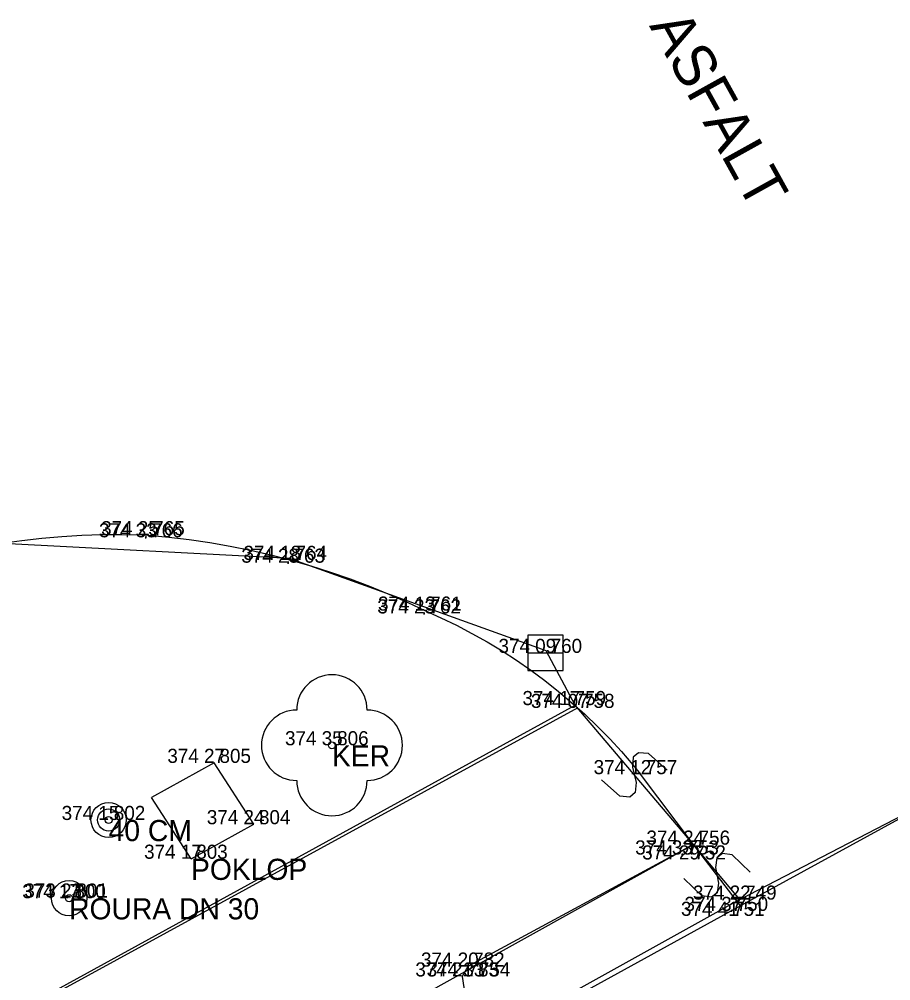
# Model space of a CAD drawing. Extents: x -601196 to -600262, y -1082523 to -1081922.
# Drawn here: x -600539.1 to -600526.73, y -1082122.59 to -1082108.95 of the extents above; entities that cross this region are included whole.
import ezdxf

# ---------------------------------------------------------------- set-up
doc = ezdxf.new("R2010")
doc.units = 0
for name, color, linetype in [('Vrstva 1', 7, 'Continuous'), ('Vrstva 10', 7, 'Continuous'), ('Vrstva 11', 7, 'Continuous'), ('Vrstva 2', 7, 'Continuous'), ('Vrstva 20', 7, 'Continuous'), ('Vrstva 22', 7, 'Continuous'), ('Vrstva 25', 7, 'Continuous'), ('Vrstva 27', 7, 'Continuous'), ('Vrstva 3', 7, 'Continuous'), ('Vrstva 40', 7, 'Continuous'), ('Vrstva 47', 7, 'Continuous'), ('Vrstva 5', 7, 'Continuous'), ('Vrstva 63', 7, 'Continuous')]:
    doc.layers.add(name, color=color, linetype=linetype)

msp = doc.modelspace()

# ---------------------------------------------------------------- linework, layer by layer
at = {"layer": 'Vrstva 1'}
for p, q in [((-600537.3, -1082116.3), (-600537.3, -1082116.3)), ((-600537.27, -1082116.27), (-600537.27, -1082116.27)), ((-600535.25, -1082116.62), (-600535.25, -1082116.62)), ((-600535.28, -1082116.66), (-600535.28, -1082116.66)), ((-600533.34, -1082117.34), (-600533.34, -1082117.34)), ((-600533.35, -1082117.38), (-600533.35, -1082117.38)), ((-600531.63, -1082117.94), (-600531.63, -1082117.94)), ((-600531.29, -1082118.68), (-600531.29, -1082118.68)), ((-600531.17, -1082118.72), (-600531.17, -1082118.72)), ((-600534.66, -1082119.25), (-600534.66, -1082119.25)), ((-600536.33, -1082119.5), (-600536.33, -1082119.5)), ((-600530.28, -1082119.66), (-600530.28, -1082119.66)), ((-600537.83, -1082120.31), (-600537.83, -1082120.31)), ((-600535.77, -1082120.37), (-600535.77, -1082120.37)), ((-600529.53, -1082120.66), (-600529.53, -1082120.66)), ((-600536.66, -1082120.86), (-600536.66, -1082120.86)), ((-600529.69, -1082120.8), (-600529.69, -1082120.8)), ((-600529.59, -1082120.87), (-600529.59, -1082120.87)), ((-600538.39, -1082121.42), (-600538.39, -1082121.42)), ((-600538.36, -1082121.41), (-600538.36, -1082121.41)), ((-600528.87, -1082121.44), (-600528.87, -1082121.44)), ((-600529.04, -1082121.67), (-600529.04, -1082121.67)), ((-600528.99, -1082121.6), (-600528.99, -1082121.6)), ((-600532.73, -1082122.39), (-600532.73, -1082122.39)), ((-600532.81, -1082122.53), (-600532.81, -1082122.53)), ((-600532.65, -1082122.53), (-600532.65, -1082122.53))]:
    msp.add_line(p, q, dxfattribs=at)
at = {"layer": 'Vrstva 10'}
for p, q in [((-600529.53, -1082120.66), (-600530.28, -1082119.66)), ((-600528.87, -1082121.44), (-600529.53, -1082120.66))]:
    msp.add_line(p, q, dxfattribs=at)
for points in [[(-600541.8, -1082117.1), (-600541.537, -1082116.99), (-600541.271, -1082116.888), (-600541.002, -1082116.793), (-600540.731, -1082116.706), (-600540.457, -1082116.626), (-600540.182, -1082116.554), (-600539.904, -1082116.49), (-600539.625, -1082116.433), (-600539.344, -1082116.385), (-600539.062, -1082116.344), (-600538.779, -1082116.311), (-600538.495, -1082116.286), (-600538.21, -1082116.269), (-600537.925, -1082116.26), (-600537.64, -1082116.259), (-600537.356, -1082116.266), (-600537.27, -1082116.27)], [(-600537.27, -1082116.27), (-600536.977, -1082116.297), (-600536.685, -1082116.331), (-600536.394, -1082116.374), (-600536.104, -1082116.424), (-600535.815, -1082116.482), (-600535.528, -1082116.548), (-600535.243, -1082116.622), (-600534.96, -1082116.703), (-600534.68, -1082116.792), (-600534.402, -1082116.889), (-600534.127, -1082116.993), (-600533.854, -1082117.105), (-600533.585, -1082117.224), (-600533.34, -1082117.34)], [(-600533.34, -1082117.34), (-600533.114, -1082117.44), (-600532.892, -1082117.547), (-600532.673, -1082117.662), (-600532.458, -1082117.783), (-600532.246, -1082117.911), (-600532.039, -1082118.045), (-600531.835, -1082118.186), (-600531.637, -1082118.333), (-600531.443, -1082118.487), (-600531.254, -1082118.646), (-600531.07, -1082118.811), (-600530.891, -1082118.982), (-600530.718, -1082119.159), (-600530.551, -1082119.34), (-600530.389, -1082119.527), (-600530.28, -1082119.66)]]:
    msp.add_lwpolyline(points, dxfattribs=at)
at = {"layer": 'Vrstva 11'}
for p, q in [((-600531.17, -1082118.72), (-600547.47, -1082127.62)), ((-600536.33, -1082119.5), (-600537.22, -1082119.99)), ((-600535.77, -1082120.37), (-600536.33, -1082119.5)), ((-600536.66, -1082120.86), (-600537.22, -1082119.99)), ((-600536.66, -1082120.86), (-600535.77, -1082120.37)), ((-600529.53, -1082120.66), (-600532.73, -1082122.39)), ((-600532.73, -1082122.39), (-600532.81, -1082122.53)), ((-600532.81, -1082122.53), (-600532.65, -1082123.58))]:
    msp.add_line(p, q, dxfattribs=at)
at = {"layer": 'Vrstva 20'}
for p, q in [((-600537.31, -1082116.3), (-600537.29, -1082116.3)), ((-600537.3, -1082116.285), (-600537.3, -1082116.3)), ((-600537.3, -1082116.315), (-600537.3, -1082116.3)), ((-600535.28, -1082116.645), (-600535.28, -1082116.66)), ((-600535.29, -1082116.66), (-600535.27, -1082116.66)), ((-600535.28, -1082116.675), (-600535.28, -1082116.66)), ((-600533.36, -1082117.38), (-600533.34, -1082117.38)), ((-600533.35, -1082117.365), (-600533.35, -1082117.38)), ((-600533.35, -1082117.395), (-600533.35, -1082117.38)), ((-600531.3, -1082118.68), (-600531.28, -1082118.68)), ((-600531.29, -1082118.665), (-600531.29, -1082118.68)), ((-600531.29, -1082118.695), (-600531.29, -1082118.68)), ((-600529.7, -1082120.8), (-600529.68, -1082120.8)), ((-600529.69, -1082120.785), (-600529.69, -1082120.8)), ((-600529.69, -1082120.815), (-600529.69, -1082120.8)), ((-600529, -1082121.6), (-600528.98, -1082121.6)), ((-600528.99, -1082121.585), (-600528.99, -1082121.6)), ((-600528.99, -1082121.615), (-600528.99, -1082121.6))]:
    msp.add_line(p, q, dxfattribs=at)
at = {"layer": 'Vrstva 22'}
msp.add_circle((-600534.66, -1082119.25), 0.05, dxfattribs=at)
for centre, start, end in [((-600534.66, -1082118.75), 0, 180), ((-600535.16, -1082119.25), 90, 270), ((-600534.16, -1082119.25), 270, 90), ((-600534.66, -1082119.75), 180, 0)]:
    msp.add_arc(centre, 0.5, start, end, dxfattribs=at)
at = {"layer": 'Vrstva 25'}
for centre, radius in [((-600537.83, -1082120.31), 0.25), ((-600537.83, -1082120.31), 0.158), ((-600537.83, -1082120.31), 0.05), ((-600538.39, -1082121.42), 0.25), ((-600538.39, -1082121.42), 0.05)]:
    msp.add_circle(centre, radius, dxfattribs=at)
at = {"layer": 'Vrstva 27'}
msp.add_line((-600531.88, -1082117.94), (-600531.38, -1082117.94), dxfattribs=at)
msp.add_lwpolyline([(-600531.88, -1082118.19), (-600531.38, -1082118.19), (-600531.38, -1082117.69), (-600531.88, -1082117.69)], close=True, dxfattribs=at)
at = {"layer": 'Vrstva 47'}
for p, q in [((-600535.26, -1082116.6), (-600539.24, -1082116.39)), ((-600531.62, -1082117.91), (-600535.26, -1082116.6)), ((-600531.21, -1082118.68), (-600531.62, -1082117.91)), ((-600547.4, -1082127.56), (-600531.21, -1082118.68)), ((-600529.53, -1082120.66), (-600531.21, -1082118.68)), ((-600530.308, -1082119.355), (-600530.385, -1082119.42)), ((-600530.167, -1082119.367), (-600530.308, -1082119.355)), ((-600529.903, -1082119.601), (-600530.167, -1082119.367)), ((-600530.385, -1082119.42), (-600530.396, -1082119.561)), ((-600530.396, -1082119.561), (-600530.343, -1082119.778)), ((-600525.4, -1082119.63), (-600528.86, -1082121.53)), ((-600530.572, -1082119.972), (-600530.836, -1082119.738)), ((-600530.343, -1082119.778), (-600530.354, -1082119.919)), ((-600530.354, -1082119.919), (-600530.431, -1082119.984)), ((-600530.431, -1082119.984), (-600530.572, -1082119.972)), ((-600546.73, -1082130.21), (-600529.53, -1082120.66)), ((-600528.86, -1082121.53), (-600529.53, -1082120.66)), ((-600529.198, -1082120.845), (-600529.216, -1082120.985)), ((-600529.118, -1082120.784), (-600529.198, -1082120.845)), ((-600528.978, -1082120.802), (-600529.118, -1082120.784)), ((-600528.725, -1082121.049), (-600528.978, -1082120.802)), ((-600529.216, -1082120.985), (-600529.173, -1082121.204)), ((-600529.411, -1082121.387), (-600529.664, -1082121.14)), ((-600529.173, -1082121.204), (-600529.191, -1082121.344)), ((-600529.271, -1082121.406), (-600529.411, -1082121.387)), ((-600529.191, -1082121.344), (-600529.271, -1082121.406)), ((-600528.86, -1082121.53), (-600545.34, -1082130.56))]:
    msp.add_line(p, q, dxfattribs=at)
at = {"layer": 'Vrstva 5'}
for q in [(-600525.37, -1082119.62), (-600545.37, -1082130.57)]:
    msp.add_line((-600528.87, -1082121.44), q, dxfattribs=at)

# ---------------------------------------------------------------- texts
at = {"layer": 'Vrstva 2'}
for s, p in [(' 766', (-600537.3, -1082116.3)), (' 765', (-600537.27, -1082116.27)), (' 763', (-600535.28, -1082116.66)), (' 764', (-600535.25, -1082116.62)), (' 762', (-600533.35, -1082117.38)), (' 761', (-600533.34, -1082117.34)), (' 760', (-600531.63, -1082117.94)), (' 759', (-600531.29, -1082118.68)), (' 758', (-600531.17, -1082118.72)), (' 806', (-600534.66, -1082119.25)), (' 805', (-600536.33, -1082119.5)), (' 757', (-600530.28, -1082119.66)), (' 802', (-600537.83, -1082120.31)), (' 804', (-600535.77, -1082120.37)), (' 756', (-600529.53, -1082120.66)), (' 753', (-600529.69, -1082120.8)), (' 803', (-600536.66, -1082120.86)), (' 752', (-600529.59, -1082120.87)), (' 800', (-600538.39, -1082121.42)), (' 801', (-600538.36, -1082121.41)), (' 749', (-600528.87, -1082121.44)), (' 750', (-600528.99, -1082121.6)), (' 751', (-600529.04, -1082121.67)), (' 782', (-600532.73, -1082122.39)), (' 783', (-600532.81, -1082122.53)), (' 754', (-600532.65, -1082122.53))]:
    msp.add_text(s, height=0.2, dxfattribs=at).set_placement(p)
at = {"layer": 'Vrstva 3'}
for s, p in [('374 33 ', (-600537.966, -1082116.3)), ('374 25 ', (-600537.936, -1082116.27)), ('374 28 ', (-600535.946, -1082116.66)), ('374 18 ', (-600535.916, -1082116.62)), ('374 23 ', (-600534.016, -1082117.38)), ('374 13 ', (-600534.006, -1082117.34)), ('374 09 ', (-600532.296, -1082117.94)), ('374 17 ', (-600531.956, -1082118.68)), ('374 07 ', (-600531.836, -1082118.72)), ('374 35 ', (-600535.326, -1082119.25)), ('374 27 ', (-600536.996, -1082119.5)), ('374 12 ', (-600530.946, -1082119.66)), ('374 15 ', (-600538.496, -1082120.31)), ('374 24 ', (-600536.436, -1082120.37)), ('374 24 ', (-600530.196, -1082120.66)), ('374 33 ', (-600530.356, -1082120.8)), ('374 17 ', (-600537.326, -1082120.86)), ('374 29 ', (-600530.256, -1082120.87)), ('374 17 ', (-600539.056, -1082121.42)), ('373 23 ', (-600539.026, -1082121.41)), ('374 22 ', (-600529.536, -1082121.44)), ('374 37 ', (-600529.656, -1082121.6)), ('374 41 ', (-600529.706, -1082121.67)), ('374 20 ', (-600533.396, -1082122.39)), ('374 21 ', (-600533.476, -1082122.53)), ('374 33 ', (-600533.316, -1082122.53))]:
    msp.add_text(s, height=0.2, dxfattribs=at).set_placement(p)
at = {"layer": 'Vrstva 40'}
msp.add_text('ASFALT', height=0.6, rotation=299.0467, dxfattribs=at).set_placement((-600530.162, -1082109.043))
at = {"layer": 'Vrstva 63'}
for s, p in [('KER', (-600534.66, -1082119.55)), ('40 CM', (-600537.83, -1082120.61)), ('POKLOP', (-600536.66, -1082121.16)), ('ROURA DN 30', (-600538.39, -1082121.72))]:
    msp.add_text(s, height=0.3, dxfattribs=at).set_placement(p)

doc.saveas('drawing.dxf')
